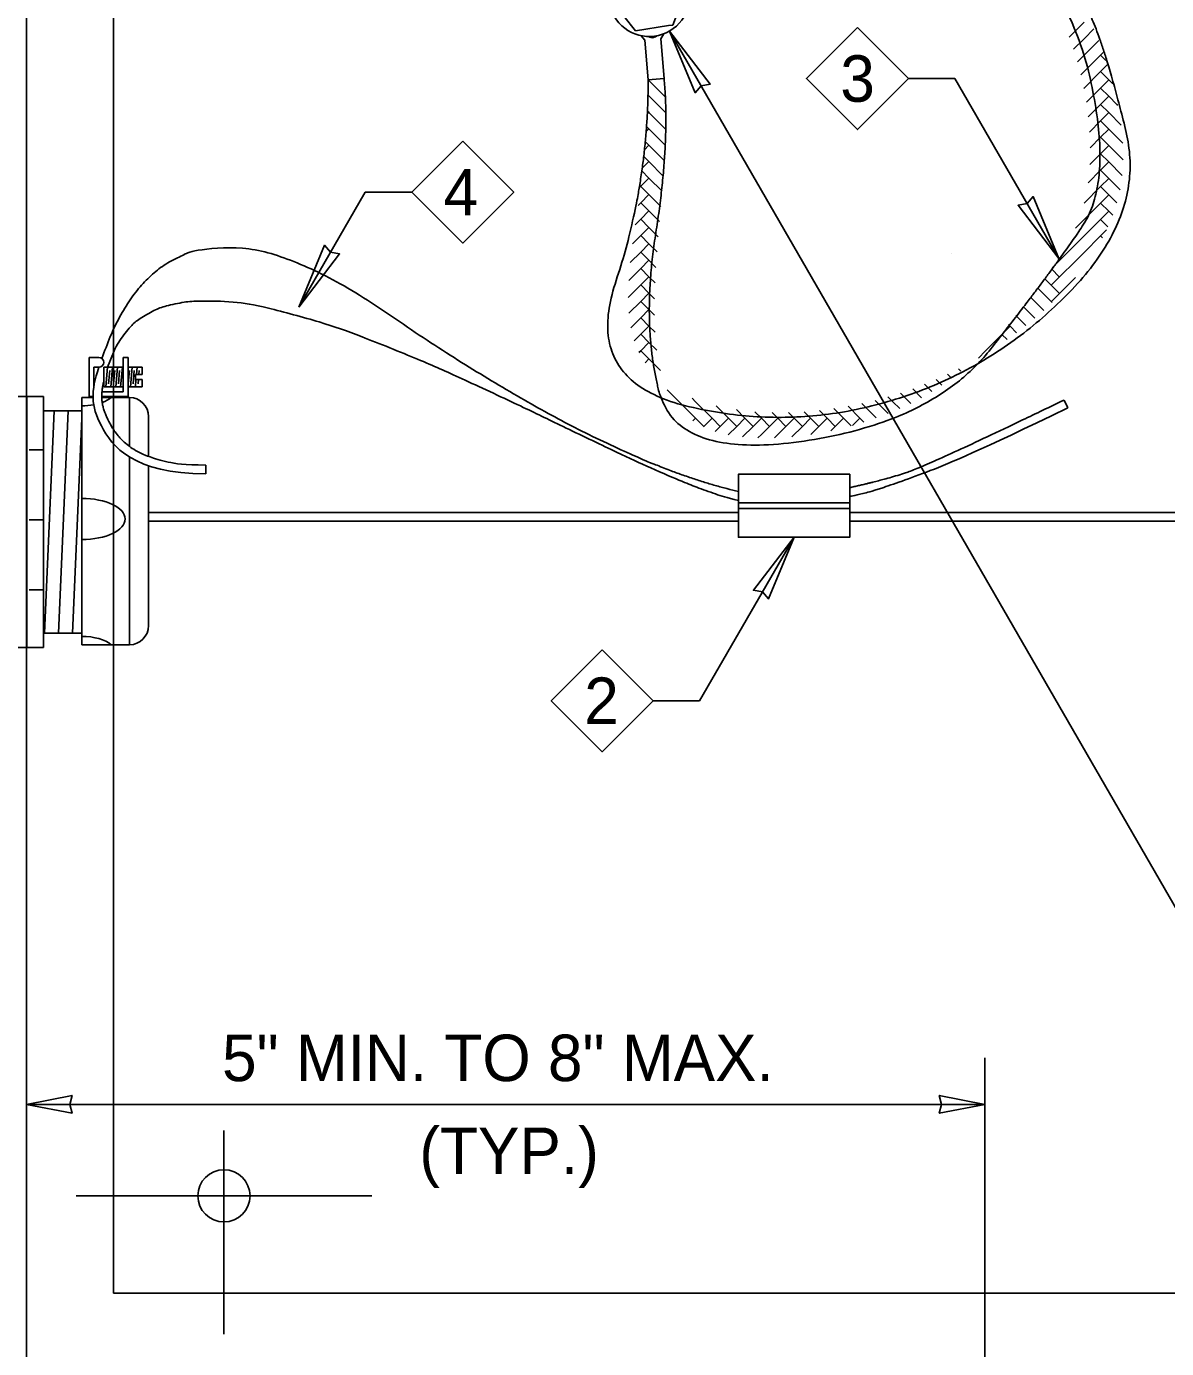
# Model space of a CAD drawing. Extents: x 99862 to 104211, y 98939 to 102076.
# Drawn here: x 100609.8 to 101002.4, y 101326.4 to 101781.5 of the extents above; entities that cross this region are included whole.
import ezdxf

# ---------------------------------------------------------------- set-up
doc = ezdxf.new("R2010")
doc.units = 0
for name, color, linetype in [('Level 1', 7, 'Continuous'), ('Level 15', 7, 'Continuous'), ('Level 20', 7, 'Continuous'), ('Level 22', 7, 'Continuous'), ('Level 4', 7, 'Continuous'), ('Level 5', 7, 'Continuous'), ('Level 7', 7, 'Continuous'), ('Level 8', 7, 'Continuous')]:
    doc.layers.add(name, color=color, linetype=linetype)

msp = doc.modelspace()

# ---------------------------------------------------------------- linework, layer by layer
at = {"layer": 'Level 1'}
for p, q in [((100609.83, 101315.45), (100609.83, 101855.45)), ((100639.83, 101345.45), (100639.83, 101825.45)), ((100928.38, 101703.45), (100928.38, 101703.45)), ((100639.83, 101585.45), (100639.83, 101345.45)), ((101659.83, 101345.45), (100639.83, 101345.45))]:
    msp.add_line(p, q, dxfattribs=at)
msp.add_circle((100677.83, 101378.96), 8.98, dxfattribs=at)
at = {"layer": 'Level 15'}
for p, q in [((100831.24, 101779.89), (101023.92, 101446.15)), ((100913.49, 101763.55), (100929.49, 101763.55)), ((100965.23, 101701.65), (100929.49, 101763.55)), ((100703.66, 101684.9), (100726.48, 101724.43)), ((100742.48, 101724.43), (100726.48, 101724.43)), ((100874.11, 101605.68), (100841.61, 101549.39)), ((100825.61, 101549.39), (100841.61, 101549.39)), ((100609.83, 101410.45), (100939.83, 101410.45)), ((100677.83, 101401.47), (100677.83, 101331.4)), ((100728.73, 101378.96), (100626.93, 101378.96))]:
    msp.add_line(p, q, dxfattribs=at)
for points in [[(100831.24, 101779.89), (100845.24, 101761.61), (100842.12, 101761.04), (100840.07, 101758.63)], [(100965.23, 101701.65), (100951.23, 101719.93), (100954.34, 101720.5), (100956.4, 101722.91)], [(100703.66, 101684.9), (100717.66, 101703.18), (100714.55, 101703.76), (100712.49, 101706.16)], [(100874.11, 101605.68), (100860.11, 101587.4), (100863.22, 101586.82), (100865.28, 101584.41)], [(100609.83, 101410.45), (100625.56, 101407.37), (100624.83, 101410.45), (100625.56, 101413.54)], [(100939.83, 101410.45), (100924.11, 101407.37), (100924.84, 101410.45), (100924.11, 101413.54)]]:
    msp.add_lwpolyline(points, close=True, dxfattribs=at)
msp.add_lwpolyline([(100939.83, 101426.45), (100939.83, 101209.94)], dxfattribs=at)
at = {"layer": 'Level 20'}
for points in [[(100895.94, 101781.1), (100913.49, 101763.55), (100895.94, 101745.99), (100878.38, 101763.55)], [(100760.03, 101741.98), (100777.59, 101724.43), (100760.03, 101706.88), (100742.48, 101724.43)], [(100808.05, 101566.94), (100825.61, 101549.39), (100808.05, 101531.83), (100790.5, 101549.39)]]:
    msp.add_lwpolyline(points, close=True, dxfattribs=at)
at = {"layer": 'Level 22'}
msp.add_arc((100824.23, 101792.03), 14.01, 289.0455, 289.0346, dxfattribs=at)
at = {"layer": 'Level 4'}
for p, q in [((100616.07, 101572.61), (100619.41, 101649.13)), ((100620.85, 101572.61), (100624.19, 101649.13)), ((100625.64, 101572.61), (100628.86, 101646.47)), ((100628.86, 101572.61), (100615.7, 101572.61))]:
    msp.add_line(p, q, dxfattribs=at)
for points in [[(100830.87, 101781.75), (100832.33, 101781.97), (100836.99, 101794.02), (100828.89, 101804.07), (100816.13, 101802.08), (100811.47, 101790.04), (100819.57, 101779.98), (100830.87, 101781.75)], [(100615.7, 101649.13), (100628.86, 101649.13)]]:
    msp.add_lwpolyline(points, dxfattribs=at)
at = {"layer": 'Level 5'}
for p, q in [((100628.86, 101653.76), (100628.86, 101568.65)), ((100628.86, 101653.76), (100632.76, 101653.76)), ((100635.76, 101653.76), (100638.59, 101653.76)), ((100638.59, 101653.76), (100642.3, 101653.76)), ((100642.3, 101653.76), (100645.31, 101653.76)), ((100645.31, 101653.76), (100645.31, 101636.93)), ((100651.89, 101647.18), (100651.89, 101633.45)), ((100645.31, 101633.32), (100645.31, 101589.02)), ((100651.89, 101630.27), (100651.89, 101575.23)), ((100645.31, 101568.65), (100645.31, 101589.02)), ((100628.86, 101568.65), (100642.3, 101568.65)), ((100642.3, 101568.65), (100645.31, 101568.65))]:
    msp.add_line(p, q, dxfattribs=at)
for centre, start, end in [((100645.31, 101647.18), 0, 90), ((100645.31, 101575.23), 270, 360)]:
    msp.add_arc(centre, 6.58, start, end, dxfattribs=at)
for centre, major_axis, start_param, end_param in [((100628.76, 101656.33), (-11.62, 0), 1.579687, 1.944365), ((100628.76, 101656.33), (-11.62, 0), 2.234056, 2.650471), ((100628.73, 101611.94), (-15.1, 0), 1.579813, 4.703498), ((100628.76, 101566.07), (-11.62, 0), 3.632714, 4.703498)]:
    msp.add_ellipse(centre, major_axis=major_axis, ratio=0.470588, start_param=start_param, end_param=end_param, dxfattribs=at)
at = {"layer": 'Level 7'}
for p, q in [((100615.7, 101654.07), (100615.7, 101567.69)), ((100615.7, 101635.77), (100610.77, 101635.77)), ((100615.7, 101611.65), (100610.77, 101611.65)), ((100610.77, 101587.52), (100615.7, 101587.52))]:
    msp.add_line(p, q, dxfattribs=at)
msp.add_lwpolyline([(100602.91, 101654.09), (100609.92, 101654.09), (100609.92, 101567.66), (100602.91, 101567.66)], close=True, dxfattribs=at)
for points in [[(100609.95, 101654.07), (100615.7, 101654.07)], [(100609.95, 101567.69), (100615.7, 101567.69)]]:
    msp.add_lwpolyline(points, dxfattribs=at)
at = {"layer": 'Level 8'}
for p, q in [((100968.87, 101777.8), (100973.98, 101782.91)), ((100822.75, 101776.75), (100821.46, 101778.29)), ((100829.24, 101778.94), (100828.22, 101777.2)), ((100977.36, 101780.63), (100973.98, 101777.25)), ((100823.89, 101763.06), (100822.75, 101776.75)), ((100828.22, 101777.2), (100829.36, 101763.52)), ((100970.35, 101773.63), (100973.98, 101777.25)), ((100979.07, 101776.69), (100973.98, 101771.6)), ((100971.69, 101769.31), (100973.98, 101771.6)), ((100979.63, 101771.59), (100973.98, 101765.94)), ((100979.63, 101771.59), (100980.57, 101772.53)), ((100979.63, 101771.59), (100981.49, 101769.74)), ((100972.88, 101764.84), (100973.98, 101765.94)), ((100979.63, 101765.94), (100973.98, 101760.28)), ((100979.63, 101765.94), (100981.95, 101768.26)), ((100979.63, 101765.94), (100982.46, 101763.11)), ((100829.36, 101763.52), (100823.89, 101763.06)), ((100829.77, 101757.21), (100823.92, 101763.06)), ((100973.9, 101760.2), (100973.98, 101760.28)), ((100979.63, 101760.28), (100974.74, 101755.38)), ((100979.63, 101760.28), (100982.46, 101763.11)), ((100979.63, 101760.28), (100982.46, 101757.45)), ((100983.84, 101761.73), (100982.46, 101763.11)), ((100829.88, 101751.82), (100823.82, 101757.88)), ((100979.63, 101754.62), (100982.46, 101757.45)), ((100985.29, 101754.62), (100982.46, 101757.45)), ((100823.52, 101751.27), (100824.14, 101751.9)), ((100829.87, 101746.17), (100823.59, 101752.45)), ((100823.87, 101752.17), (100824.14, 101751.9)), ((100979.63, 101754.62), (100975.38, 101750.37)), ((100979.63, 101754.62), (100982.46, 101751.8)), ((100979.63, 101754.62), (100979.63, 101754.62)), ((100979.63, 101748.97), (100982.46, 101751.8)), ((100986.73, 101747.53), (100982.46, 101751.8)), ((100985.59, 101754.33), (100985.29, 101754.62)), ((100829.76, 101740.63), (100823.24, 101747.15)), ((100979.63, 101748.97), (100975.81, 101745.14)), ((100979.63, 101748.97), (100982.46, 101746.14)), ((100822.78, 101741.94), (100824.14, 101740.58)), ((100823.08, 101745.17), (100824.14, 101746.24)), ((100979.63, 101743.31), (100976.02, 101739.7)), ((100979.63, 101743.31), (100982.46, 101746.14)), ((100979.63, 101743.31), (100982.46, 101740.48)), ((100987.34, 101741.26), (100982.46, 101746.14)), ((100822.48, 101738.92), (100824.14, 101740.58)), ((100829.48, 101735.25), (100824.14, 101740.58)), ((100979.63, 101737.65), (100975.9, 101733.92)), ((100979.63, 101737.65), (100982.46, 101740.48)), ((100979.63, 101737.65), (100982.46, 101734.83)), ((100987.43, 101735.52), (100982.46, 101740.48)), ((100821.75, 101732.53), (100824.14, 101734.93)), ((100822.25, 101736.82), (100824.14, 101734.93)), ((100829.1, 101729.97), (100824.14, 101734.93)), ((100979.63, 101732), (100982.46, 101734.83)), ((100987.08, 101730.21), (100982.46, 101734.83)), ((100820.92, 101726.05), (100824.14, 101729.27)), ((100821.66, 101731.76), (100824.14, 101729.27)), ((100828.68, 101724.73), (100824.14, 101729.27)), ((100979.63, 101732), (100975.32, 101727.68)), ((100979.63, 101732), (100982.46, 101729.17)), ((100979.63, 101726.34), (100982.46, 101729.17)), ((100986.34, 101725.29), (100982.46, 101729.17)), ((100821.02, 101726.74), (100824.14, 101723.61)), ((100979.63, 101726.34), (100973.98, 101720.68)), ((100979.63, 101726.34), (100982.46, 101723.51)), ((100821.32, 101720.78), (100820.4, 101719.87)), ((100821.32, 101720.78), (100824.14, 101723.61)), ((100821.32, 101720.78), (100824.14, 101717.96)), ((100828.23, 101719.52), (100824.14, 101723.61)), ((100973.95, 101720.66), (100973.98, 101720.68)), ((100979.63, 101720.68), (100973.98, 101715.03)), ((100979.63, 101720.68), (100982.46, 101723.51)), ((100979.63, 101720.68), (100982.46, 101717.86)), ((100985.25, 101720.72), (100982.46, 101723.51)), ((100821.32, 101715.13), (100819.4, 101713.21)), ((100821.32, 101715.13), (100824.14, 101717.96)), ((100821.32, 101715.13), (100824.14, 101712.3)), ((100827.79, 101714.31), (100824.14, 101717.96)), ((100970.97, 101712.02), (100973.98, 101715.03)), ((100979.63, 101715.03), (100973.98, 101709.37)), ((100979.63, 101715.03), (100982.46, 101717.86)), ((100979.63, 101715.03), (100982.19, 101712.47)), ((100983.85, 101716.46), (100982.46, 101717.86)), ((100821.32, 101709.47), (100824.14, 101712.3)), ((100827.35, 101709.09), (100824.14, 101712.3)), ((100979.63, 101709.37), (100981.72, 101711.46)), ((100821.32, 101709.47), (100818.48, 101706.63)), ((100821.32, 101709.47), (100824.14, 101706.64)), ((100821.32, 101703.81), (100824.14, 101706.64)), ((100826.95, 101703.84), (100824.14, 101706.64)), ((100962.96, 101698.35), (100973.98, 101709.37)), ((100979.63, 101709.37), (100973.98, 101703.71)), ((100979.63, 101709.37), (100980.32, 101708.69)), ((100821.32, 101703.81), (100817.72, 101700.22)), ((100821.32, 101703.81), (100824.14, 101700.99)), ((100821.32, 101698.16), (100824.14, 101700.99)), ((100826.58, 101698.55), (100824.14, 101700.99)), ((100962.66, 101692.4), (100973.98, 101703.71)), ((100965.49, 101700.89), (100965.02, 101701.36)), ((100821.32, 101698.16), (100817.22, 101694.06)), ((100821.32, 101698.16), (100824.14, 101695.33)), ((100821.32, 101698.16), (100821.32, 101698.16)), ((100965.49, 101695.23), (100962.71, 101698.01)), ((100821.32, 101692.5), (100817.05, 101688.23)), ((100821.32, 101692.5), (100824.14, 101695.33)), ((100821.32, 101692.5), (100824.14, 101689.67)), ((100826.29, 101693.18), (100824.14, 101695.33)), ((100965.49, 101689.57), (100960.34, 101694.73)), ((100962.66, 101686.74), (100971.02, 101695.09)), ((100821.32, 101686.84), (100824.14, 101689.67)), ((100826.1, 101687.71), (100824.14, 101689.67)), ((100960.05, 101683.7), (100955.48, 101688.27)), ((100962.97, 101686.44), (100957.92, 101691.49)), ((100821.32, 101686.84), (100817.26, 101682.79)), ((100821.32, 101686.84), (100824.14, 101684.02)), ((100821.32, 101681.19), (100824.14, 101684.02)), ((100826.06, 101682.1), (100824.14, 101684.02)), ((100957.02, 101681.07), (100953, 101685.1)), ((100821.32, 101681.19), (100817.9, 101677.77)), ((100821.32, 101681.19), (100824.14, 101678.36)), ((100821.32, 101675.53), (100824.14, 101678.36)), ((100826.25, 101676.25), (100824.14, 101678.36)), ((100945.69, 101675.43), (100948.52, 101678.26)), ((100947.9, 101678.88), (100948.52, 101678.26)), ((100950.74, 101676.04), (100948.52, 101678.26)), ((100953.92, 101678.51), (100950.47, 101681.97)), ((100821.32, 101675.53), (100819.04, 101673.26)), ((100821.32, 101675.53), (100824.14, 101672.7)), ((100945.69, 101675.43), (100940.04, 101669.77)), ((100945.69, 101675.43), (100947.45, 101673.68)), ((100821.32, 101669.87), (100820.69, 101669.25)), ((100821.32, 101669.87), (100824.14, 101672.7)), ((100821.32, 101669.87), (100824.14, 101667.04)), ((100826.84, 101670.01), (100824.14, 101672.7)), ((100937.58, 101667.32), (100940.04, 101669.77)), ((100643.17, 101667.52), (100643.17, 101655.74)), ((100644.85, 101654.06), (100644.85, 101667.52)), ((100822.81, 101665.71), (100824.14, 101667.05)), ((100828.15, 101663.04), (100824.14, 101667.05)), ((100633.08, 101657.8), (100633.08, 101664.15)), ((100633.08, 101664.15), (100634.76, 101664.15)), ((100636.46, 101664.15), (100643.17, 101664.15)), ((100637.79, 101664.15), (100637.2, 101657.43)), ((100638.54, 101663.08), (100638.14, 101658.5)), ((100639.48, 101664.15), (100638.89, 101657.43)), ((100640.23, 101663.08), (100639.83, 101658.5)), ((100641.16, 101664.15), (100640.58, 101657.43)), ((100641.92, 101663.08), (100641.51, 101658.5)), ((100642.85, 101664.15), (100642.26, 101657.43)), ((100644.85, 101664.15), (100649.71, 101664.15)), ((100645.29, 101663.08), (100644.89, 101658.5)), ((100646.23, 101664.15), (100645.64, 101657.43)), ((100646.98, 101663.08), (100646.58, 101658.5)), ((100649.71, 101661.63), (100647.37, 101661.63)), ((100647.92, 101664.15), (100647.7, 101661.63)), ((100648.67, 101663.08), (100648.54, 101661.63)), ((100649.71, 101664.15), (100649.71, 101661.63)), ((100923.06, 101659.99), (100925.03, 101658.02)), ((100926.96, 101661.75), (100928.34, 101660.36)), ((100930.76, 101663.6), (100931.53, 101662.83)), ((100643.17, 101655.74), (100635.83, 101655.74)), ((100643.17, 101657.43), (100636.46, 101657.43)), ((100649.71, 101657.43), (100644.85, 101657.43)), ((100647.55, 101659.95), (100647.33, 101657.43)), ((100647.37, 101659.95), (100649.71, 101659.95)), ((100648.39, 101659.95), (100648.27, 101658.5)), ((100649.71, 101659.95), (100649.71, 101657.43)), ((100830.47, 101656.41), (100834.56, 101652.32)), ((100914.98, 101656.75), (100918.04, 101653.69)), ((100919.07, 101658.32), (100921.6, 101655.79)), ((100840.22, 101646.66), (100834.56, 101652.32)), ((100839, 101653.54), (100840.22, 101652.32)), ((100845.88, 101646.66), (100840.22, 101652.32)), ((100851.53, 101646.66), (100847.29, 101650.91)), ((100902.41, 101646.7), (100897.43, 101651.68)), ((100902, 101652.76), (100902.45, 101652.32)), ((100906.51, 101648.25), (100902.45, 101652.32)), ((100906.45, 101653.97), (100908.1, 101652.32)), ((100910.49, 101649.93), (100908.1, 101652.32)), ((100910.78, 101655.3), (100913.76, 101652.32)), ((100914.33, 101651.74), (100913.76, 101652.32)), ((100967.1, 101652.88), (100968.41, 101650.18)), ((100840.22, 101646.66), (100839.3, 101645.74)), ((100840.22, 101646.66), (100843.05, 101643.83)), ((100845.88, 101646.66), (100843.05, 101643.83)), ((100845.88, 101646.66), (100848.71, 101643.83)), ((100851.53, 101646.66), (100848.71, 101643.83)), ((100851.53, 101646.66), (100854.36, 101643.83)), ((100857.19, 101646.66), (100854.26, 101649.59)), ((100857.19, 101646.66), (100854.36, 101643.83)), ((100857.19, 101646.66), (100860.02, 101643.83)), ((100862.85, 101646.66), (100860.02, 101643.83)), ((100862.85, 101646.66), (100860.64, 101648.87)), ((100862.85, 101646.66), (100862.85, 101646.66)), ((100862.85, 101646.66), (100865.68, 101643.83)), ((100868.5, 101646.66), (100865.68, 101643.83)), ((100868.5, 101646.66), (100866.56, 101648.6)), ((100868.5, 101646.66), (100871.33, 101643.83)), ((100874.16, 101646.66), (100871.33, 101643.83)), ((100874.16, 101646.66), (100872.22, 101648.6)), ((100874.16, 101646.66), (100876.99, 101643.83)), ((100879.82, 101646.66), (100876.99, 101643.83)), ((100879.82, 101646.66), (100877.63, 101648.85)), ((100879.82, 101646.66), (100882.65, 101643.83)), ((100885.47, 101646.66), (100882.65, 101643.83)), ((100885.47, 101646.66), (100882.83, 101649.3)), ((100885.47, 101646.66), (100888.3, 101643.83)), ((100891.13, 101646.66), (100887.86, 101649.94)), ((100891.13, 101646.66), (100888.3, 101643.83)), ((100891.13, 101646.66), (100893.79, 101644)), ((100896.79, 101646.66), (100892.72, 101650.73)), ((100896.79, 101646.66), (100894.27, 101644.14)), ((100896.79, 101646.66), (100898.16, 101645.29)), ((100842.89, 101643.68), (100843.05, 101643.83)), ((100846.96, 101642.08), (100848.71, 101643.83)), ((100851.46, 101640.93), (100854.36, 101643.83)), ((100856.38, 101640.19), (100860.02, 101643.83)), ((100862.85, 101641), (100865.68, 101643.83)), ((100867.34, 101639.84), (100871.33, 101643.83)), ((100873.4, 101640.24), (100876.99, 101643.83)), ((100879.86, 101641.05), (100882.65, 101643.83)), ((100886.78, 101642.31), (100888.3, 101643.83)), ((100861.67, 101639.83), (100862.85, 101641)), ((100671.59, 101627.52), (100671.59, 101630.52)), ((100854.94, 101617.51), (100893.28, 101617.51)), ((100854.94, 101615.51), (100893.28, 101615.51)), ((100651.89, 101614.2), (100854.94, 101614.21)), ((100651.89, 101611.2), (100854.94, 101611.21)), ((100893.28, 101614.21), (101205.47, 101614.23)), ((100893.28, 101611.21), (101205.47, 101611.23))]:
    msp.add_line(p, q, dxfattribs=at)
for points in [[(100634.76, 101667.52), (100631.4, 101667.52)], [(100631.4, 101667.52), (100631.4, 101654.06)], [(100644.85, 101667.52), (100643.17, 101667.52)], [(100636.46, 101657.43), (100636.46, 101664.15)], [(100647.37, 101661.63), (100647.37, 101659.95)], [(100631.4, 101654.06), (100632.75, 101654.06)], [(100635.75, 101654.06), (100644.85, 101654.06)], [(100854.94, 101615.51), (100854.94, 101627.34), (100893.28, 101627.34), (100893.28, 101617.51)], [(100893.28, 101617.51), (100893.28, 101605.68), (100854.94, 101605.68), (100854.94, 101615.51)]]:
    msp.add_lwpolyline(points, dxfattribs=at)
for start, end in [(0, 90), (270, 360)]:
    msp.add_arc((100634.76, 101665.83), 1.68, start, end, dxfattribs=at)
for centre, major_axis, start_param, end_param in [((100808.04, 101795.17), (17.49, -17.48), 5.950489, 6.242362), ((100839.68, 101797.81), (-14.35, -20.13), 0.040823, 0.332697)]:
    msp.add_ellipse(centre, major_axis=major_axis, ratio=0.111087, start_param=start_param, end_param=end_param, dxfattribs=at)
for points, degree in [([(100944.15, 101842.45), (101107.53, 101842.45), (101039.43, 101690.35), (101143.99, 101626.49), (101195.04, 101621.15), (101205.47, 101621.29)], 3), ([(100944.15, 101839.45), (100967.09, 101839.45), (100986.06, 101837.94), (101017.37, 101832.51), (101029.69, 101828.59), (101044.23, 101821.41), (101048.41, 101818.8), (101055.66, 101813.22), (101058.72, 101810.26), (101063.93, 101804.02), (101066.08, 101800.74), (101069.63, 101793.92), (101071.04, 101790.37), (101074.38, 101779.35), (101075.43, 101771.54), (101076.39, 101755.48), (101076.31, 101747.25), (101076.32, 101730.96), (101076.42, 101722.9), (101077.53, 101713.23), (101077.8, 101711.32), (101078.46, 101707.56), (101078.84, 101705.71), (101080.12, 101700.25), (101081.17, 101696.72), (101087.35, 101679.69), (101095.2, 101667.96), (101114.51, 101648.3), (101125.97, 101640.35), (101150.43, 101628.04), (101163.42, 101623.67), (101177.79, 101620.69), (101179.38, 101620.39), (101182.57, 101619.83), (101184.17, 101619.58), (101189.08, 101618.92), (101192.47, 101618.6), (101199.06, 101618.29), (101202.13, 101618.24), (101205.47, 101618.29)], 3), ([(100918.97, 101835.82), (100964.93, 101807.35), (100984.81, 101729.31), (100961.38, 101695.13), (100921.98, 101645.4), (100833.94, 101632.26), (100821.52, 101678.79), (100831.46, 101741.65), (100829.36, 101763.52)], 2), ([(100823.89, 101763.06), (100823.88, 101726.98), (100801.4, 101659.5), (100873.1, 101642.1), (100943.74, 101663.77), (100995.21, 101717.39), (100981.5, 101773.52), (100971.08, 101796.23), (100931.67, 101816.48), (100912.84, 101832.75)], 2), ([(100635.82, 101667.14), (100658.55, 101734.56), (100807.22, 101632.42), (100854.94, 101621.42)], 2), ([(100637.79, 101664.15), (100639.99, 101670.1), (100641.74, 101673.33), (100645.97, 101678.64), (100648.44, 101680.74), (100654.16, 101684.02), (100657.4, 101685.2), (100664.62, 101686.72), (100668.6, 101687.05), (100681.47, 101686.86), (100691.28, 101685.15), (100712.27, 101679.46), (100723.47, 101675.49), (100746.31, 101666.31), (100757.95, 101661.1), (100780.78, 101650.46), (100791.96, 101645.02), (100812.98, 101634.94), (100822.82, 101630.3), (100835.95, 101624.68), (100840.06, 101623.03), (100847.43, 101620.38), (100850.74, 101619.35), (100854.94, 101618.34)], 3), ([(100671.59, 101627.52), (100646.65, 101627.52), (100631.94, 101646.29), (100631.97, 101655.81), (100634.76, 101664.15)], 3), ([(100671.59, 101630.52), (100664.04, 101630.52), (100658.26, 101631.42), (100651.6, 101633.49), (100649.71, 101634.29), (100646.47, 101636.05), (100645.12, 101637.01), (100642.8, 101638.99), (100641.84, 101640.02), (100640.2, 101642.1), (100639.51, 101643.16), (100638.62, 101644.73), (100638.34, 101645.25), (100637.82, 101646.27), (100637.59, 101646.76), (100636.96, 101648.18), (100636.63, 101649.06), (100636.14, 101650.75), (100635.97, 101651.56), (100635.77, 101653.16), (100635.73, 101653.97), (100635.8, 101655.66), (100635.9, 101656.55), (100636.18, 101658.09), (100636.31, 101658.7), (100636.46, 101659.34)], 3), ([(100893.28, 101622.73), (100904.2, 101625.15), (100920.08, 101630.2), (100967.1, 101652.88)], 2), ([(100893.28, 101619.66), (100893.53, 101619.72), (100893.78, 101619.77), (100897.77, 101620.66), (100902.1, 101621.8), (100919.53, 101627.75), (100937.11, 101635.08), (100968.41, 101650.18)], 3)]:
    msp.add_open_spline(points, degree=degree, dxfattribs=at)

# ---------------------------------------------------------------- texts
at = {"layer": 'Level 20'}
for s, p in [('3', (100890.03, 101755.55)), ('4', (100753.44, 101716.43)), ('2', (100801.88, 101541.39)), ('5" MIN. TO 8" MAX.', (100677.18, 101418.45)), ('(TYP.)', (100745.1, 101386.45))]:
    msp.add_text(s, height=16, dxfattribs=at).set_placement(p)

doc.saveas('drawing.dxf')
